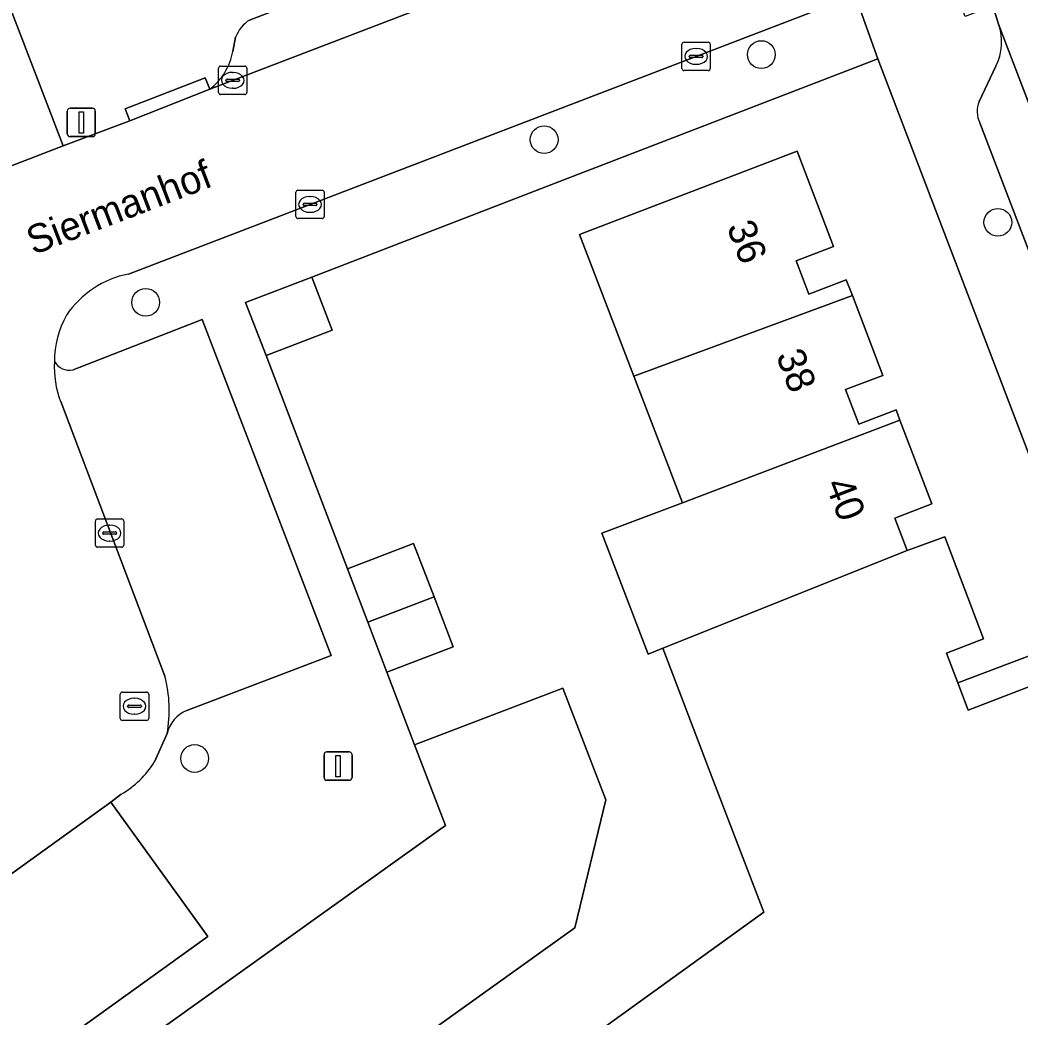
# Model space of a CAD drawing. Extents: x 159262 to 160143, y 383399 to 384319.
# Drawn here: x 159510.15 to 159545.42, y 383543.65 to 383578.83 of the extents above; entities that cross this region are included whole.
import ezdxf

# ---------------------------------------------------------------- set-up
doc = ezdxf.new("R2010")
doc.units = 0
for name, color, linetype in [('IMGEO_Boom', 7, 'Continuous'), ('IMGEO_Erf', 7, 'Continuous'), ('IMGEO_Groenvoorziening', 7, 'Continuous'), ('IMGEO_Haag', 7, 'Continuous'), ('IMGEO_Kolk', 7, 'Continuous'), ('IMGEO_Lichtmast', 7, 'Continuous'), ('IMGEO_Muur', 7, 'Continuous'), ('IMGEO_Openbare_ruimte_label', 7, 'Continuous'), ('IMGEO_Pand', 7, 'Continuous'), ('IMGEO_Pand_nummerreeks', 7, 'Continuous'), ('IMGEO_Parkeervlak_open', 7, 'Continuous'), ('IMGEO_Rijbaan_lokaal_gesloten', 7, 'Continuous'), ('IMGEO_Rijbaan_lokaal_open', 7, 'Continuous'), ('IMGEO_Rioolput', 7, 'Continuous'), ('IMGEO_Voetpad_open', 7, 'Continuous')]:
    doc.layers.add(name, color=color, linetype=linetype)

msp = doc.modelspace()

# ---------------------------------------------------------------- linework, layer by layer
at = {"layer": 'IMGEO_Boom'}
for centre in [(159536.297, 383577.615), (159528.64, 383574.616), (159544.64, 383571.699), (159514.589, 383568.879), (159516.316, 383552.798)]:
    msp.add_circle(centre, 0.489, dxfattribs=at)
at = {"layer": 'IMGEO_Erf'}
msp.add_lwpolyline([(159523.125, 383537.808), (159536.386, 383547.381), (159534.559, 383552.153), (159532.823, 383556.687), (159532.308, 383556.481), (159530.678, 383560.74), (159533.514, 383561.816), (159531.806, 383566.279), (159529.892, 383571.277), (159537.559, 383574.211), (159538.845, 383570.851), (159537.53, 383570.348), (159537.98, 383569.172), (159539.295, 383569.675), (159539.509, 383569.116), (159540.585, 383566.305), (159539.27, 383565.802), (159539.734, 383564.588), (159541.05, 383565.091), (159541.189, 383564.728), (159542.318, 383561.777), (159541.002, 383561.274), (159541.44, 383560.13), (159542.765, 383560.61), (159544.14, 383557.017), (159542.824, 383556.514), (159543.225, 383555.465), (159548.112, 383557.308), (159540.404, 383577.462), (159529.18, 383573.136), (159520.445, 383569.769), (159521.165, 383567.903), (159518.832, 383567.003), (159521.7, 383559.485), (159524.036, 383560.378), (159524.757, 383558.494), (159525.429, 383556.735), (159523.093, 383555.842), (159524.071, 383553.282), (159528.742, 383555.068), (159529.302, 383555.282), (159530.81, 383551.341), (159529.716, 383546.827), (159517.098, 383537.79)], dxfattribs=at)
at = {"layer": 'IMGEO_Groenvoorziening'}
msp.add_lwpolyline([(159548.112, 383557.308), (159543.225, 383555.465), (159543.592, 383554.506), (159546.766, 383555.72), (159550.116, 383546.969), (159552.34, 383546.267), (159550.578, 383550.859)], close=True, dxfattribs=at)
at = {"layer": 'IMGEO_Haag'}
msp.add_lwpolyline([(159548.112, 383557.308), (159543.225, 383555.465), (159543.592, 383554.506), (159546.766, 383555.72), (159550.116, 383546.969), (159552.34, 383546.267), (159550.578, 383550.859)], close=True, dxfattribs=at)
at = {"layer": 'IMGEO_Kolk'}
for p, q in [((159533.574, 383578.051), (159534.426, 383578.051)), ((159533.499, 383577.125), (159533.499, 383577.977)), ((159533.987, 383577.831), (159534.012, 383577.831)), ((159534.5, 383577.977), (159534.5, 383577.125)), ((159533.758, 383577.545), (159533.758, 383577.557)), ((159534.196, 383577.508), (159533.798, 383577.508)), ((159533.801, 383577.594), (159534.199, 383577.594)), ((159534.242, 383577.557), (159534.242, 383577.545)), ((159517.155, 383576.281), (159517.155, 383577.133)), ((159517.23, 383577.207), (159518.082, 383577.207)), ((159517.643, 383576.987), (159517.668, 383576.987)), ((159518.156, 383577.133), (159518.156, 383576.281)), ((159534.426, 383577.051), (159533.574, 383577.051)), ((159534.01, 383577.271), (159533.985, 383577.271)), ((159517.414, 383576.701), (159517.414, 383576.713)), ((159517.852, 383576.664), (159517.454, 383576.664)), ((159517.457, 383576.75), (159517.855, 383576.75)), ((159517.898, 383576.713), (159517.898, 383576.701)), ((159517.666, 383576.427), (159517.641, 383576.427)), ((159518.082, 383576.207), (159517.23, 383576.207)), ((159519.882, 383571.907), (159519.882, 383572.759)), ((159519.957, 383572.833), (159520.809, 383572.833)), ((159520.883, 383572.759), (159520.883, 383571.907)), ((159520.184, 383572.376), (159520.582, 383572.376)), ((159520.37, 383572.613), (159520.395, 383572.613)), ((159520.141, 383572.327), (159520.141, 383572.339)), ((159520.579, 383572.29), (159520.181, 383572.29)), ((159520.393, 383572.053), (159520.368, 383572.053)), ((159520.625, 383572.339), (159520.625, 383572.327)), ((159520.809, 383571.833), (159519.957, 383571.833)), ((159512.814, 383560.318), (159512.814, 383561.17)), ((159512.889, 383561.244), (159513.741, 383561.244)), ((159513.815, 383561.17), (159513.815, 383560.318)), ((159513.073, 383560.738), (159513.073, 383560.75)), ((159513.116, 383560.787), (159513.514, 383560.787)), ((159513.302, 383561.024), (159513.327, 383561.024)), ((159513.557, 383560.75), (159513.557, 383560.738)), ((159513.511, 383560.701), (159513.113, 383560.701)), ((159513.325, 383560.464), (159513.3, 383560.464)), ((159513.741, 383560.244), (159512.889, 383560.244))]:
    msp.add_line(p, q, dxfattribs=at)
for points in [[(159533.574, 383578.051), (159534.426, 383578.051)], [(159533.499, 383577.125), (159533.499, 383577.977)], [(159534.5, 383577.977), (159534.5, 383577.125)], [(159517.155, 383576.281), (159517.155, 383577.133)], [(159517.23, 383577.207), (159518.082, 383577.207)], [(159518.156, 383577.133), (159518.156, 383576.281)], [(159534.426, 383577.051), (159533.574, 383577.051)], [(159518.082, 383576.207), (159517.23, 383576.207)], [(159519.882, 383571.907), (159519.882, 383572.759)], [(159519.957, 383572.833), (159520.809, 383572.833)], [(159520.883, 383572.759), (159520.883, 383571.907)], [(159520.809, 383571.833), (159519.957, 383571.833)], [(159512.814, 383560.318), (159512.814, 383561.17)], [(159512.889, 383561.244), (159513.741, 383561.244)], [(159513.815, 383561.17), (159513.815, 383560.318)], [(159513.741, 383560.244), (159512.889, 383560.244)]]:
    msp.add_lwpolyline(points, dxfattribs=at)
for centre, radius, start, end in [((159533.576, 383577.975), 0.0765, 91.552, 178.448), ((159533.576, 383577.975), 0.0765, 91.552, 178.448), ((159534.424, 383577.975), 0.0765, 1.552, 88.448), ((159534.424, 383577.975), 0.0765, 1.552, 88.448), ((159533.798, 383577.554), 0.0403, 85.8775, 175.7526), ((159533.795, 383577.544), 0.0366, 178.938, 274.7102), ((159534.199, 383577.551), 0.043, 264.8664, 352.4533), ((159534.203, 383577.556), 0.0386, 1.7309, 96.639), ((159517.232, 383577.131), 0.0765, 91.552, 178.448), ((159517.232, 383577.131), 0.0765, 91.552, 178.448), ((159518.08, 383577.131), 0.0765, 1.552, 88.448), ((159518.08, 383577.131), 0.0765, 1.552, 88.448), ((159533.576, 383577.127), 0.0765, 181.552, 268.448), ((159533.576, 383577.127), 0.0765, 181.552, 268.448), ((159534.424, 383577.127), 0.0765, 271.552, 358.448), ((159534.424, 383577.127), 0.0765, 271.552, 358.448), ((159517.454, 383576.71), 0.0403, 85.8775, 175.7526), ((159517.451, 383576.7), 0.0366, 178.938, 274.7102), ((159517.855, 383576.707), 0.043, 264.8664, 352.4533), ((159517.859, 383576.712), 0.0386, 1.7309, 96.639), ((159517.232, 383576.283), 0.0765, 181.552, 268.448), ((159517.232, 383576.283), 0.0765, 181.552, 268.448), ((159518.08, 383576.283), 0.0765, 271.552, 358.448), ((159518.08, 383576.283), 0.0765, 271.552, 358.448), ((159519.959, 383572.757), 0.0765, 91.552, 178.448), ((159519.959, 383572.757), 0.0765, 91.552, 178.448), ((159520.807, 383572.757), 0.0765, 1.552, 88.448), ((159520.807, 383572.757), 0.0765, 1.552, 88.448), ((159520.181, 383572.336), 0.0403, 85.8775, 175.7526), ((159520.586, 383572.338), 0.0386, 1.7309, 96.639), ((159520.178, 383572.326), 0.0366, 178.938, 274.7102), ((159520.582, 383572.333), 0.043, 264.8664, 352.4533), ((159519.959, 383571.909), 0.0765, 181.552, 268.448), ((159519.959, 383571.909), 0.0765, 181.552, 268.448), ((159520.807, 383571.909), 0.0765, 271.552, 358.448), ((159520.807, 383571.909), 0.0765, 271.552, 358.448), ((159512.891, 383561.168), 0.0765, 91.552, 178.448), ((159512.891, 383561.168), 0.0765, 91.552, 178.448), ((159513.739, 383561.168), 0.0765, 1.552, 88.448), ((159513.739, 383561.168), 0.0765, 1.552, 88.448), ((159513.113, 383560.747), 0.0403, 85.8775, 175.7526), ((159513.11, 383560.737), 0.0366, 178.938, 274.7102), ((159513.514, 383560.744), 0.043, 264.8664, 352.4533), ((159513.518, 383560.749), 0.0386, 1.7309, 96.639), ((159512.891, 383560.32), 0.0765, 181.552, 268.448), ((159512.891, 383560.32), 0.0765, 181.552, 268.448), ((159513.739, 383560.32), 0.0765, 271.552, 358.448), ((159513.739, 383560.32), 0.0765, 271.552, 358.448)]:
    msp.add_arc(centre, radius, start, end, dxfattribs=at)
for centre, major_axis, ratio, start_param, end_param in [((159533.986, 383577.551), (-0.387, 0.002), 0.722429, 4.712389, 7.853982), ((159534.011, 383577.551), (-0.39, 0.002), 0.717154, 1.570796, 4.712389), ((159517.642, 383576.707), (-0.387, 0.002), 0.722429, 4.712389, 7.853982), ((159517.667, 383576.707), (-0.39, 0.002), 0.717154, 1.570796, 4.712389), ((159520.369, 383572.333), (-0.387, 0.002), 0.722429, 4.712389, 7.853982), ((159520.394, 383572.333), (-0.39, 0.002), 0.717154, 1.570796, 4.712389), ((159513.301, 383560.744), (-0.387, 0.002), 0.722429, 4.712389, 7.853982), ((159513.326, 383560.744), (-0.39, 0.002), 0.717154, 1.570796, 4.712389)]:
    msp.add_ellipse(centre, major_axis=major_axis, ratio=ratio, start_param=start_param, end_param=end_param, dxfattribs=at)
at = {"layer": 'IMGEO_Lichtmast'}
for p, q in [((159511.819, 383574.824), (159511.819, 383575.624)), ((159511.819, 383575.624), (159511.819, 383574.824)), ((159511.919, 383575.724), (159512.709, 383575.724)), ((159512.709, 383575.724), (159511.919, 383575.724)), ((159512.809, 383575.624), (159512.809, 383574.824)), ((159512.809, 383574.824), (159512.809, 383575.624)), ((159512.709, 383574.724), (159511.919, 383574.724)), ((159511.919, 383574.724), (159512.709, 383574.724)), ((159520.976, 383553.031), (159521.766, 383553.031)), ((159521.766, 383553.031), (159520.976, 383553.031)), ((159520.876, 383552.131), (159520.876, 383552.931)), ((159520.876, 383552.931), (159520.876, 383552.131)), ((159521.866, 383552.931), (159521.866, 383552.131)), ((159521.866, 383552.131), (159521.866, 383552.931)), ((159521.766, 383552.031), (159520.976, 383552.031)), ((159520.976, 383552.031), (159521.766, 383552.031))]:
    msp.add_line(p, q, dxfattribs=at)
for points in [[(159512.239, 383575.599), (159512.389, 383575.599), (159512.389, 383574.849), (159512.239, 383574.849), (159512.239, 383575.599)], [(159521.296, 383552.906), (159521.446, 383552.906), (159521.446, 383552.156), (159521.296, 383552.156), (159521.296, 383552.906)]]:
    msp.add_lwpolyline(points, dxfattribs=at)
for centre, start, end in [((159511.919, 383575.624), 90, 180), ((159511.919, 383575.624), 90, 180), ((159512.709, 383575.624), 0, 90), ((159512.709, 383575.624), 360, 90), ((159511.919, 383574.824), 180, 270), ((159511.919, 383574.824), 180, 270), ((159512.709, 383574.824), 270, 0), ((159512.709, 383574.824), 270, 0), ((159520.976, 383552.931), 90, 180), ((159520.976, 383552.931), 90, 180), ((159521.766, 383552.931), 0, 90), ((159521.766, 383552.931), 360, 90), ((159520.976, 383552.131), 180, 270), ((159520.976, 383552.131), 180, 270), ((159521.766, 383552.131), 270, 0), ((159521.766, 383552.131), 270, 0)]:
    msp.add_arc(centre, 0.1, start, end, dxfattribs=at)
at = {"layer": 'IMGEO_Muur'}
for points in [[(159520.445, 383569.769), (159529.18, 383573.136)], [(159521.7, 383559.485), (159518.832, 383567.003)], [(159523.093, 383555.842), (159524.071, 383553.282)]]:
    msp.add_lwpolyline(points, dxfattribs=at)
at = {"layer": 'IMGEO_Pand'}
for points in [[(159531.806, 383566.279), (159539.509, 383569.116), (159539.295, 383569.675), (159537.98, 383569.172), (159537.53, 383570.348), (159538.845, 383570.851), (159537.559, 383574.211), (159529.892, 383571.277)], [(159520.445, 383569.769), (159518.112, 383568.869), (159518.832, 383567.003), (159521.165, 383567.903)], [(159533.514, 383561.816), (159541.189, 383564.728), (159541.05, 383565.091), (159539.734, 383564.588), (159539.27, 383565.802), (159540.585, 383566.305), (159539.509, 383569.116), (159531.806, 383566.279)], [(159541.44, 383560.13), (159541.002, 383561.274), (159542.318, 383561.777), (159541.189, 383564.728), (159533.514, 383561.816), (159530.678, 383560.74), (159532.308, 383556.481), (159532.823, 383556.687)], [(159522.418, 383557.606), (159524.757, 383558.494), (159524.036, 383560.378), (159521.7, 383559.485)], [(159522.418, 383557.606), (159523.093, 383555.842), (159525.429, 383556.735), (159524.757, 383558.494)], [(159528.742, 383555.068), (159524.071, 383553.282), (159525.16, 383550.433), (159513.845, 383542.332), (159516.756, 383538.267), (159517.098, 383537.79), (159529.716, 383546.827), (159530.81, 383551.341), (159529.302, 383555.282)]]:
    msp.add_lwpolyline(points, close=True, dxfattribs=at)
msp.add_lwpolyline([(159546.766, 383555.72), (159543.592, 383554.506), (159543.225, 383555.465), (159542.824, 383556.514), (159544.14, 383557.017), (159542.765, 383560.61), (159541.44, 383560.13), (159532.823, 383556.687), (159534.559, 383552.153), (159536.386, 383547.381), (159523.125, 383537.808)], dxfattribs=at)
at = {"layer": 'IMGEO_Parkeervlak_open'}
for points in [[(159533.217, 383584.583), (159518.252, 383578.834)], [(159516.852, 383576.397), (159536.716, 383584.016)], [(159487.574, 383565.048), (159489.966, 383565.954), (159500, 383569.902), (159511.675, 383574.392), (159509.54, 383579.977), (159500, 383576.298), (159491.132, 383572.812), (159484.177, 383570.154), (159486.256, 383564.773)], [(159555.658, 383550.011), (159554.634, 383552.639), (159553.482, 383555.649), (159544.661, 383578.691)], [(159517.76, 383578.23), (159517.661, 383577.726)], [(159544.575, 383577.204), (159543.986, 383575.959)], [(159544.003, 383575.206), (159553.012, 383551.691)], [(159516.042, 383554.486), (159521.129, 383556.431), (159516.584, 383568.276), (159512.025, 383566.504)], [(159511.589, 383565.378), (159515.265, 383555.697)]]:
    msp.add_lwpolyline(points, dxfattribs=at)
msp.add_lwpolyline([(159513.356, 383551.255), (159500, 383541.647), (159496.488, 383539.005), (159498.715, 383535.965), (159499.839, 383534.344), (159500, 383534.46), (159516.778, 383546.526)], close=True, dxfattribs=at)
for centre, radius, start, end in [((159518.891, 383577.811), 1.206, 121.9841, 159.6855), ((159542.875, 383578.048), 1.898, 333.584, 19.796), ((159515.515, 383578.122), 2.182, 307.7848, 349.5551), ((159544.823, 383575.601), 0.911, 156.8671, 205.7195), ((159514.74, 383566.595), 3.378, 176.6829, 201.1081), ((159511.893, 383567.098), 0.608, 210.4017, 282.5501), ((159510.775, 383554.518), 4.643, 349.5377, 14.7108), ((159516.454, 383553.42), 1.143, 111.1381, 167.1031)]:
    msp.add_arc(centre, radius, start, end, dxfattribs=at)
at = {"layer": 'IMGEO_Rijbaan_lokaal_gesloten'}
msp.add_lwpolyline([(159530.741, 383615.142), (159540.07, 383590.725), (159540.271, 383590.202), (159541.314, 383587.467), (159544.461, 383579.335), (159544.661, 383578.691), (159553.482, 383555.649), (159558.862, 383557.786), (159555.134, 383567.48), (159555.25, 383567.52)], dxfattribs=at)
at = {"layer": 'IMGEO_Rijbaan_lokaal_open'}
for points in [[(159513.981, 383569.878), (159539.603, 383579.714), (159537.779, 383584.462), (159536.862, 383584.072), (159536.716, 383584.016), (159516.852, 383576.397), (159514.023, 383575.279), (159511.675, 383574.392), (159500, 383569.902), (159489.966, 383565.954), (159487.574, 383565.048)], [(159515.265, 383555.697), (159511.589, 383565.378)], [(159514.896, 383552.674), (159515.34, 383553.675)], [(159485.905, 383545.698), (159486.755, 383544.503), (159489.801, 383540.323), (159490.035, 383540.035), (159490.689, 383539.176), (159496.038, 383538.77), (159496.488, 383539.005), (159500, 383541.647), (159513.356, 383551.255), (159513.719, 383551.536)]]:
    msp.add_lwpolyline(points, dxfattribs=at)
for centre, radius, start, end in [((159514.638, 383566.518), 3.424, 101.0651, 146.109), ((159514.748, 383566.781), 3.381, 150.8548, 179.8408), ((159514.74, 383566.595), 3.378, 176.6829, 201.1081), ((159510.775, 383554.518), 4.643, 349.5377, 14.7108), ((159511.981, 383554.511), 3.445, 300.2905, 327.7792)]:
    msp.add_arc(centre, radius, start, end, dxfattribs=at)
at = {"layer": 'IMGEO_Rioolput'}
for p, q in [((159513.767, 383555.139), (159514.619, 383555.139)), ((159513.692, 383554.213), (159513.692, 383555.065)), ((159514.18, 383554.919), (159514.205, 383554.919)), ((159514.693, 383555.065), (159514.693, 383554.213)), ((159513.951, 383554.633), (159513.951, 383554.645)), ((159514.389, 383554.596), (159513.991, 383554.596)), ((159513.994, 383554.682), (159514.392, 383554.682)), ((159514.435, 383554.645), (159514.435, 383554.633)), ((159514.619, 383554.139), (159513.767, 383554.139)), ((159514.203, 383554.359), (159514.178, 383554.359))]:
    msp.add_line(p, q, dxfattribs=at)
for points in [[(159513.767, 383555.139), (159514.619, 383555.139)], [(159513.692, 383554.213), (159513.692, 383555.065)], [(159514.693, 383555.065), (159514.693, 383554.213)], [(159514.619, 383554.139), (159513.767, 383554.139)]]:
    msp.add_lwpolyline(points, dxfattribs=at)
for centre, radius, start, end in [((159513.769, 383555.063), 0.0765, 91.552, 178.448), ((159513.769, 383555.063), 0.0765, 91.552, 178.448), ((159514.617, 383555.063), 0.0765, 1.552, 88.448), ((159514.617, 383555.063), 0.0765, 1.552, 88.448), ((159513.991, 383554.642), 0.0403, 85.8775, 175.7526), ((159513.988, 383554.632), 0.0366, 178.938, 274.7102), ((159514.392, 383554.639), 0.043, 264.8664, 352.4533), ((159514.396, 383554.644), 0.0386, 1.7309, 96.639), ((159513.769, 383554.215), 0.0765, 181.552, 268.448), ((159513.769, 383554.215), 0.0765, 181.552, 268.448), ((159514.617, 383554.215), 0.0765, 271.552, 358.448), ((159514.617, 383554.215), 0.0765, 271.552, 358.448)]:
    msp.add_arc(centre, radius, start, end, dxfattribs=at)
for centre, major_axis, ratio, start_param, end_param in [((159514.179, 383554.639), (-0.387, 0.002), 0.722429, 4.712389, 7.853982), ((159514.204, 383554.639), (-0.39, 0.002), 0.717154, 1.570796, 4.712389)]:
    msp.add_ellipse(centre, major_axis=major_axis, ratio=ratio, start_param=start_param, end_param=end_param, dxfattribs=at)
at = {"layer": 'IMGEO_Voetpad_open'}
for points in [[(159522.528, 383624.356), (159535.827, 383589.588), (159537.779, 383584.462), (159539.603, 383579.714), (159540.404, 383577.462), (159548.112, 383557.308), (159550.578, 383550.859), (159552.34, 383546.267), (159554.003, 383541.935), (159554.163, 383541.518)], [(159544.661, 383578.691), (159544.461, 383579.335), (159543.491, 383578.96), (159540.344, 383587.092), (159541.314, 383587.467), (159540.271, 383590.202), (159540.07, 383590.725)], [(159518.252, 383578.834), (159533.217, 383584.583)], [(159486.256, 383564.773), (159484.177, 383570.154), (159491.132, 383572.812), (159500, 383576.298), (159509.54, 383579.977), (159511.675, 383574.392), (159514.023, 383575.279), (159513.862, 383575.698), (159516.685, 383576.793), (159516.852, 383576.397)], [(159524.071, 383553.282), (159523.093, 383555.842), (159522.418, 383557.606), (159521.7, 383559.485), (159518.832, 383567.003), (159518.112, 383568.869), (159520.445, 383569.769), (159529.18, 383573.136), (159540.404, 383577.462), (159539.603, 383579.714), (159513.981, 383569.878)], [(159517.661, 383577.726), (159517.76, 383578.23)], [(159543.986, 383575.959), (159544.575, 383577.204)], [(159553.012, 383551.691), (159544.003, 383575.206)], [(159512.025, 383566.504), (159516.584, 383568.276), (159521.129, 383556.431), (159516.042, 383554.486)], [(159515.34, 383553.675), (159514.896, 383552.674)], [(159490.824, 383526.848), (159491.295, 383526.187), (159492.756, 383527.233), (159494.37, 383528.389), (159499.853, 383532.314), (159500, 383532.419), (159501.357, 383533.391), (159503.016, 383534.579), (159507.664, 383537.907), (159509.295, 383539.074), (159513.845, 383542.332), (159525.16, 383550.433), (159524.071, 383553.282)], [(159513.719, 383551.536), (159513.356, 383551.255), (159516.778, 383546.526), (159500, 383534.46), (159499.839, 383534.344), (159498.715, 383535.965), (159496.488, 383539.005), (159496.038, 383538.77), (159495.705, 383538.174), (159493.728, 383531.462), (159489.192, 383532.861), (159490.816, 383538.498), (159490.689, 383539.176), (159490.035, 383540.035), (159489.801, 383540.323), (159484.997, 383536.939), (159482.829, 383535.412), (159486.36, 383530.47), (159485.885, 383527.217)]]:
    msp.add_lwpolyline(points, dxfattribs=at)
msp.add_lwpolyline([(159514.023, 383575.279), (159516.852, 383576.397), (159516.685, 383576.793), (159513.862, 383575.698)], close=True, dxfattribs=at)
for centre, radius, start, end in [((159518.891, 383577.811), 1.206, 121.9841, 159.6855), ((159542.875, 383578.048), 1.898, 333.584, 19.796), ((159515.515, 383578.122), 2.182, 307.7848, 349.5551), ((159544.823, 383575.601), 0.911, 156.8671, 205.7195), ((159514.638, 383566.518), 3.424, 101.0651, 146.109), ((159514.748, 383566.781), 3.381, 150.8548, 179.8408), ((159511.893, 383567.098), 0.608, 210.4017, 282.5501), ((159516.454, 383553.42), 1.143, 111.1381, 167.1031), ((159511.981, 383554.511), 3.445, 300.2905, 327.7792)]:
    msp.add_arc(centre, radius, start, end, dxfattribs=at)

# ---------------------------------------------------------------- texts
at = {"layer": 'IMGEO_Openbare_ruimte_label'}
msp.add_text('Siermanhof', height=1, rotation=20.9717, dxfattribs=at).set_placement((159510.626, 383570.541))
at = {"layer": 'IMGEO_Pand_nummerreeks'}
for s, rotation, p in [('36', 290.9451, (159535.068, 383571.543)), ('38', 290.9451, (159536.805, 383567.007)), ('40', 290.9471, (159538.54, 383562.472))]:
    msp.add_text(s, height=1, rotation=rotation, dxfattribs=at).set_placement(p)

doc.saveas('drawing.dxf')
